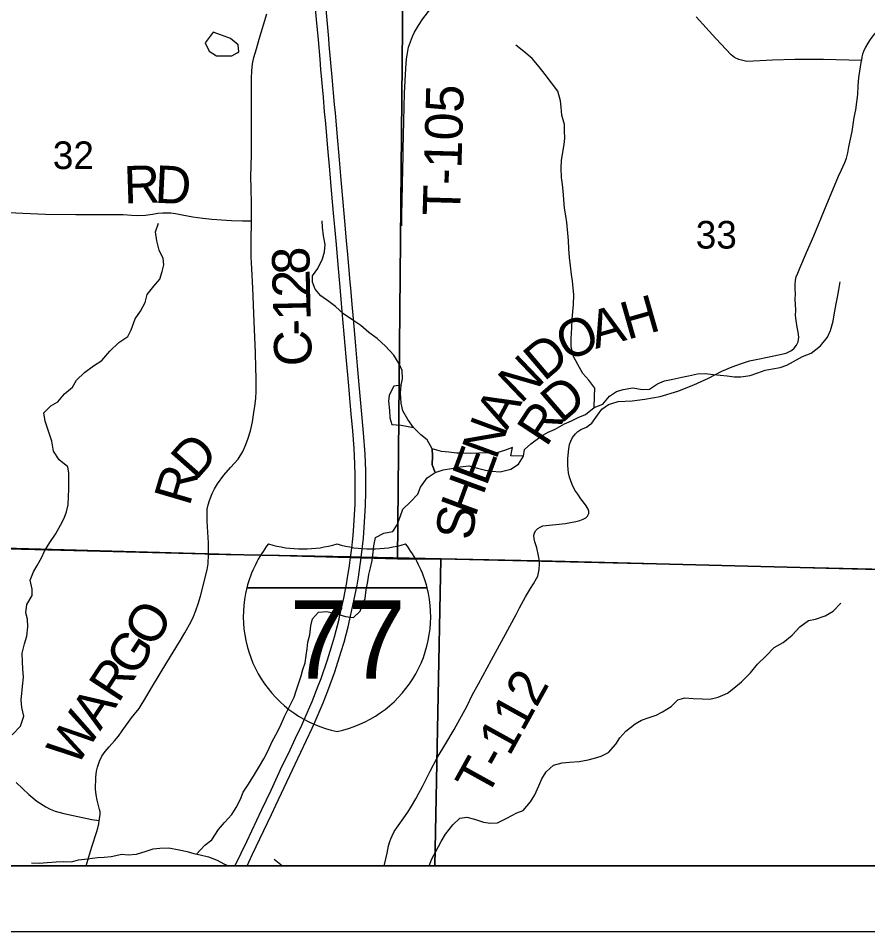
# Model space of a CAD drawing. Extents: x 0 to 34, y 0 to 22.
# Drawn here: x 28.471 to 29.759, y 14 to 15.384 of the extents above; entities that cross this region are included whole.
import ezdxf

# ---------------------------------------------------------------- set-up
doc = ezdxf.new("R2010")
doc.units = 0
for name, color, linetype in [('GM_X_Corporation', 7, 'Continuous'), ('GM_X_County_Road', 7, 'Continuous'), ('GM_X_County_Road_Text', 7, 'Continuous'), ('GM_X_Interstate_Location', 7, 'Continuous'), ('GM_X_Interstate_Route', 7, 'Continuous'), ('GM_X_Interstate_Shield', 7, 'Continuous'), ('GM_X_Minor_Lake', 7, 'Continuous'), ('GM_X_Minor_River', 7, 'Continuous'), ('GM_X_Section_Text', 7, 'Continuous'), ('GM_X_Township_Road', 7, 'Continuous'), ('GM_X_Township_Road_Text', 7, 'Continuous'), ('SH_Data', 7, 'Continuous')]:
    doc.layers.add(name, color=color, linetype=linetype)

msp = doc.modelspace()

# ---------------------------------------------------------------- linework, layer by layer
at = {"layer": 'GM_X_Corporation'}
for points in [[(23.5167, 14.1), (30.3167, 14.1), (30.3167, 18.565), (30.101, 18.5701), (29.6772, 18.5786), (29.6561, 18.5791), (29.0074, 18.5935), (28.7772, 18.6028), (28.3421, 18.6121), (27.3971, 18.6436), (27.1064, 18.6537), (27.1039, 18.5696), (27.0944, 18.0731), (27.0775, 16.888), (27.0694, 16.6556), (27.0676, 16.5549), (27.052, 15.403), (27.043, 14.755), (27.046, 14.6155), (27.01, 14.6164), (26.6535, 14.621)], [(27.0676, 16.5549), (27.052, 15.403), (27.043, 14.755), (27.046, 14.6155), (27.2076, 14.6118), (27.2151, 14.6117), (27.2601, 14.6106), (27.262, 14.6106), (27.3217, 14.6092), (27.3244, 14.6092), (28.7538, 14.5726), (28.7592, 14.5724), (28.9743, 14.568), (28.9779, 14.5679), (28.9904, 14.5676), (29.257, 14.5621), (29.2606, 14.562), (30.0913, 14.5411), (30.0947, 14.5411), (30.3167, 14.5373), (30.3167, 18.565)], [(26.0358, 14.1), (30.3167, 14.1), (30.3167, 14.5373), (30.0947, 14.5411), (30.0913, 14.5411), (29.2606, 14.562), (29.257, 14.5621), (28.9904, 14.5676), (28.9779, 14.5679), (28.9743, 14.568), (28.7592, 14.5724), (28.7538, 14.5726), (27.3244, 14.6092), (27.3217, 14.6092), (27.262, 14.6106), (27.2601, 14.6106), (27.2151, 14.6117), (27.2076, 14.6118), (27.046, 14.6155), (27.01, 14.6164), (26.6535, 14.621)]]:
    msp.add_lwpolyline(points, dxfattribs=at)
for points in [[(29.0554, 15.5858), (29.0455, 14.5648), (28.107, 14.591), (28.0653, 14.5914), (28.0603, 15.6194)], [(30.0852, 15.5935), (30.0916, 14.542), (29.1115, 14.5644), (29.0455, 14.5648), (29.0554, 15.5858)], [(28.0946, 14.1), (29.1022, 14.1), (29.1115, 14.5644), (29.0455, 14.5648), (28.107, 14.591)], [(29.1022, 14.1), (30.0878, 14.1), (30.0916, 14.542), (29.1115, 14.5644)]]:
    msp.add_lwpolyline(points, close=True, dxfattribs=at)
at = {"layer": 'GM_X_County_Road'}
for points in [[(29.8077, 15.4032), (29.7862, 15.3803), (29.7766, 15.3701), (29.7665, 15.3579), (29.7621, 15.3522), (29.7585, 15.3469), (29.755, 15.3404), (29.7523, 15.3341), (29.7506, 15.3298), (29.7497, 15.3262), (29.749, 15.3205), (29.6916, 15.322), (29.6482, 15.3218), (29.6144, 15.3211), (29.5752, 15.3187), (29.5633, 15.3221), (29.5567, 15.3252), (29.5516, 15.3291), (29.5282, 15.3538), (29.4987, 15.3865)], [(28.7593, 14.5748), (28.7593, 14.5894), (28.7579, 14.6137), (28.7574, 14.6225), (28.757, 14.6317), (28.7574, 14.6404), (28.7586, 14.6468), (28.7607, 14.6535), (28.7648, 14.6643), (28.7683, 14.6714), (28.773, 14.679), (28.7824, 14.6921), (28.7926, 14.7036), (28.8039, 14.716), (28.8114, 14.7277), (28.8149, 14.7361), (28.819, 14.7465), (28.8229, 14.7589), (28.8258, 14.7726), (28.8277, 14.7871), (28.8296, 14.7966), (28.831, 14.808), (28.8313, 14.8195), (28.8314, 14.8277), (28.8312, 14.8392), (28.831, 14.8544), (28.8306, 14.8778), (28.8283, 14.9244), (28.8265, 14.9756), (28.8247, 15.0047), (28.8239, 15.023), (28.8238, 15.0466), (28.8245, 15.0776), (28.8246, 15.1051), (28.8236, 15.1457), (28.8238, 15.1594), (28.8243, 15.1792), (28.8244, 15.2105), (28.8246, 15.2388), (28.8244, 15.2713), (28.8244, 15.2857), (28.8245, 15.2937), (28.8247, 15.3047), (28.8261, 15.3155), (28.828, 15.3249), (28.8318, 15.338), (28.8362, 15.3529), (28.8476, 15.3911)], [(28.583, 14.1304), (28.5892, 14.1502), (28.5913, 14.1571), (28.5928, 14.1633), (28.5934, 14.1686), (28.595, 14.1772), (28.5947, 14.1818), (28.5941, 14.1854), (28.5902, 14.1994), (28.5889, 14.2077), (28.5877, 14.216), (28.5886, 14.2341), (28.5896, 14.2434), (28.5911, 14.2494), (28.594, 14.2583), (28.5973, 14.266), (28.6024, 14.2731), (28.6084, 14.2801), (28.6168, 14.2892), (28.6228, 14.2963), (28.6284, 14.3043), (28.6425, 14.324), (28.6539, 14.3385), (28.664, 14.3548), (28.6742, 14.372), (28.6961, 14.4082), (28.7154, 14.4393), (28.7235, 14.4528), (28.7327, 14.47), (28.7362, 14.4777), (28.7401, 14.4871), (28.7435, 14.4969), (28.7469, 14.5087), (28.757, 14.5483), (28.7585, 14.5574), (28.7594, 14.5719), (28.7593, 14.5748)], [(28.4674, 14.2264), (28.4869, 14.2081), (28.499, 14.1981), (28.5126, 14.1894), (28.5191, 14.1858), (28.5265, 14.1826), (28.5397, 14.1793), (28.5821, 14.1703), (28.5934, 14.1686)], [(28.5739, 14.1), (28.5768, 14.11), (28.5803, 14.122), (28.583, 14.1304)]]:
    msp.add_lwpolyline(points, dxfattribs=at)
at = {"layer": 'GM_X_Interstate_Route'}
for points in [[(28.7997, 14.1), (28.8003, 14.1012), (28.8173, 14.137), (28.8399, 14.1852), (28.854, 14.2148), (28.8711, 14.2514), (28.8804, 14.2701), (28.8913, 14.2936), (28.9005, 14.3133), (28.9035, 14.3199), (28.9161, 14.3491), (28.9254, 14.3725), (28.9299, 14.384), (28.9395, 14.412), (28.9458, 14.4316), (28.9502, 14.4467), (28.9571, 14.4739), (28.9579, 14.4775), (28.9642, 14.5053), (28.9688, 14.5295), (28.9694, 14.5332), (28.9729, 14.5549), (28.9745, 14.5674), (28.9763, 14.5811), (28.9778, 14.5954), (28.9789, 14.6073), (28.9814, 14.6481), (28.9817, 14.6738), (28.9815, 14.6917), (28.9811, 14.7092), (28.9798, 14.7326), (28.9779, 14.7589), (28.9755, 14.7848), (28.9736, 14.8079), (28.9725, 14.8211), (28.9719, 14.8272), (28.968, 14.8714), (28.9666, 14.8885), (28.965, 14.9055), (28.9619, 14.9402), (28.9593, 14.971), (28.9552, 15.0167), (28.9532, 15.0414), (28.9507, 15.0685), (28.9493, 15.0836), (28.9458, 15.1234), (28.9431, 15.1548), (28.9403, 15.1874), (28.9368, 15.225), (28.9351, 15.2427), (28.9333, 15.2646), (28.9296, 15.307), (28.9284, 15.3225), (28.9257, 15.3515), (28.9229, 15.3828), (28.921, 15.4055)], [(28.8176, 14.1), (28.8255, 14.1167), (28.8546, 14.1778), (28.8611, 14.192), (28.8866, 14.2455), (28.8905, 14.2539), (28.9164, 14.3087), (28.921, 14.3188), (28.9328, 14.3469), (28.9401, 14.3651), (28.9507, 14.3937), (28.9605, 14.4246), (28.9646, 14.4391), (28.9708, 14.462), (28.9736, 14.4735), (28.9772, 14.4899), (28.9812, 14.5088), (28.9843, 14.525), (28.9864, 14.5375), (28.9906, 14.5671), (28.9942, 14.5967), (28.9964, 14.6294), (28.997, 14.6462), (28.9977, 14.6662), (28.9975, 14.6985), (28.9966, 14.7236), (28.9942, 14.756), (28.991, 14.7902), (28.9877, 14.8288), (28.9852, 14.8579), (28.9826, 14.8882), (28.9788, 14.9288), (28.977, 14.9505), (28.9748, 14.9752), (28.9739, 14.9845), (28.9703, 15.0262), (28.9684, 15.0469), (28.9661, 15.077), (28.9634, 15.1056), (28.9604, 15.1397), (28.9577, 15.1698), (28.9541, 15.2103), (28.9515, 15.2409), (28.9502, 15.2537), (28.9465, 15.2953), (28.9423, 15.3442), (28.9414, 15.3536), (28.9371, 15.4037)]]:
    msp.add_lwpolyline(points, dxfattribs=at)
at = {"layer": 'GM_X_Interstate_Shield'}
for p, q in [((28.8174, 14.5213), (29.0906, 14.5213)), ((29.0906, 14.5213), (28.8174, 14.5213)), ((29.0906, 14.5213), (28.8174, 14.5213))]:
    msp.add_line(p, q, dxfattribs=at)
for centre, start, end in [((28.9895, 14.4777), 141.669, 165.8066), ((28.9021, 14.7577), 253.0091, 286.9909), ((29.0059, 14.7577), 253.0091, 286.9909), ((28.9185, 14.4777), 14.1934, 38.331), ((28.9895, 14.4777), 165.8066, 258.463), ((28.9185, 14.4777), 281.537, 14.1934)]:
    msp.add_arc(centre, 0.1776, start, end, dxfattribs=at)
at = {"layer": 'GM_X_Minor_Lake'}
for points in [[(28.7663, 15.3632), (28.7543, 15.3473), (28.7604, 15.3348), (28.7714, 15.3276), (28.7945, 15.3277), (28.8027, 15.332)], [(28.8027, 15.332), (28.8054, 15.3334), (28.8043, 15.344), (28.7925, 15.3539), (28.7789, 15.3587), (28.7663, 15.3632)], [(29.0515, 14.8282), (29.0402, 14.827), (29.033, 14.8134), (29.0319, 14.8039), (29.0335, 14.7899), (29.0343, 14.7789), (29.0369, 14.7686), (29.051, 14.7679), (29.0699, 14.7642)], [(29.0699, 14.7642), (29.0615, 14.7763), (29.0539, 14.7896), (29.0512, 14.8009), (29.0504, 14.8161), (29.0515, 14.8282)], [(29.0984, 14.7321), (29.0988, 14.7211), (29.0981, 14.7074), (29.103, 14.6961), (29.1148, 14.6999), (29.1276, 14.7022), (29.1409, 14.7046), (29.1537, 14.7061), (29.167, 14.7028), (29.1791, 14.6994), (29.1886, 14.6979), (29.2011, 14.6972), (29.2177, 14.701), (29.2291, 14.7087), (29.2366, 14.7208)], [(29.2366, 14.7208), (29.2177, 14.7215), (29.2199, 14.7337), (29.2078, 14.7291), (29.1961, 14.726), (29.1828, 14.7256), (29.1692, 14.7255), (29.1567, 14.7247), (29.1465, 14.7254), (29.1355, 14.7254), (29.1234, 14.7269), (29.1124, 14.7276), (29.0984, 14.7321)]]:
    msp.add_lwpolyline(points, dxfattribs=at)
at = {"layer": 'GM_X_Minor_River'}
for points in [[(29.3436, 14.7944), (29.3443, 14.8114), (29.345, 14.8236), (29.3355, 14.8357), (29.3267, 14.8462), (29.3191, 14.8595), (29.3127, 14.8716), (29.3092, 14.8871), (29.3092, 14.8989), (29.3099, 14.9152), (29.3106, 14.9284), (29.3117, 14.9394), (29.3124, 14.9501), (29.3128, 14.9656), (29.312, 14.9755), (29.3108, 14.9864), (29.3096, 14.9959), (29.3081, 15.0092), (29.3065, 15.0217), (29.3054, 15.0349), (29.3049, 15.0478), (29.3038, 15.0588), (29.3026, 15.0751), (29.301, 15.085), (29.2991, 15.0967), (29.2979, 15.1096), (29.2968, 15.1229), (29.2956, 15.1323), (29.2944, 15.1429), (29.2936, 15.157), (29.2944, 15.1691), (29.2962, 15.1816), (29.2984, 15.193), (29.2996, 15.2029), (29.2991, 15.2139), (29.2987, 15.2233), (29.2949, 15.2377), (29.2937, 15.2498), (29.2929, 15.2593), (29.2887, 15.2741), (29.2789, 15.2866), (29.2697, 15.2994), (29.2606, 15.3108), (29.25, 15.3236), (29.2371, 15.3342), (29.2253, 15.3436)], [(29.103, 14.6961), (29.0981, 14.7074), (29.0988, 14.7211), (29.0984, 14.7321), (29.0908, 14.7457), (29.0813, 14.7529), (29.0699, 14.7642), (29.0615, 14.7763), (29.0539, 14.7896), (29.0512, 14.8009), (29.0504, 14.8161), (29.0515, 14.8282), (29.0534, 14.8381), (29.053, 14.8506), (29.048, 14.8608), (29.04, 14.8737), (29.0275, 14.8876), (29.015, 14.899), (29.0021, 14.9084), (28.9899, 14.919), (28.9763, 14.9277), (28.9637, 14.9363), (28.9516, 14.9477), (28.9417, 14.9552), (28.9296, 14.9635), (28.9208, 14.9741), (28.9166, 14.9843), (28.917, 14.9942), (28.9249, 15.0052), (28.9321, 15.0196), (28.9351, 15.0302), (28.9362, 15.0416), (28.9335, 15.0549), (28.9319, 15.0678), (28.9315, 15.0776)], [(28.4617, 14.2984), (28.4742, 14.3117), (28.479, 14.3265), (28.476, 14.3398), (28.4752, 14.3511), (28.4774, 14.3716), (28.4789, 14.3857), (28.4777, 14.3985), (28.4773, 14.4088), (28.4769, 14.422), (28.4802, 14.4361), (28.4836, 14.4479), (28.4851, 14.4619), (28.4846, 14.4736), (28.4823, 14.4831), (28.4838, 14.496), (28.4921, 14.5097), (28.4921, 14.5192), (28.489, 14.5328), (28.4939, 14.5453), (28.4995, 14.5552), (28.506, 14.5666), (28.5105, 14.5768), (28.5188, 14.5901), (28.527, 14.6027), (28.535, 14.616), (28.5402, 14.627), (28.544, 14.6365), (28.5462, 14.6471), (28.5469, 14.66), (28.5473, 14.6702), (28.5476, 14.682), (28.5476, 14.6949), (28.5461, 14.7047), (28.5328, 14.7153), (28.5244, 14.7282), (28.5217, 14.7433), (28.5167, 14.7588), (28.5118, 14.7736), (28.5095, 14.7865), (28.5204, 14.7971), (28.531, 14.8032), (28.5408, 14.8154), (28.5529, 14.8253), (28.5593, 14.836), (28.5714, 14.8477), (28.5846, 14.8577), (28.5974, 14.8657), (28.6095, 14.8797), (28.6235, 14.893), (28.6367, 14.9022), (28.642, 14.9124), (28.648, 14.9291), (28.6559, 14.9405), (28.6634, 14.9535), (28.6661, 14.966), (28.6762, 14.9785), (28.6853, 14.9892), (28.689, 15.0006), (28.6913, 15.0108), (28.6905, 15.0203), (28.6844, 15.0328), (28.681, 15.0472), (28.6786, 15.0608), (28.6835, 15.0737)], [(29.6141, 14.8529), (29.6258, 14.8552), (29.636, 14.8587), (29.6459, 14.864), (29.6599, 14.8717), (29.6727, 14.877), (29.6867, 14.8881), (29.6973, 14.901), (29.7021, 14.9112), (29.7063, 14.9256), (29.7081, 14.9382), (29.7107, 14.9514), (29.7126, 14.9617), (29.7145, 14.9727), (29.7167, 14.9852)], [(28.7408, 14.1178), (28.7534, 14.1311), (28.7643, 14.1395), (28.7741, 14.1547), (28.7836, 14.1657), (28.7945, 14.1775), (28.8009, 14.1885), (28.8077, 14.201), (28.8118, 14.2117), (28.8186, 14.2223), (28.8273, 14.2356), (28.8367, 14.2508), (28.8431, 14.2622), (28.8491, 14.2736), (28.8559, 14.2884), (28.8638, 14.3029), (28.8691, 14.3146), (28.8743, 14.326), (28.8792, 14.3363), (28.889, 14.3553), (28.892, 14.3651), (28.8961, 14.3773), (28.8995, 14.3879), (28.9021, 14.3974), (28.9059, 14.4073), (28.9074, 14.4186), (28.9088, 14.4289), (28.9099, 14.4387), (28.9126, 14.4501), (28.9144, 14.4638), (28.917, 14.474), (28.9257, 14.4843), (28.9386, 14.4851), (28.9518, 14.4821), (28.967, 14.478), (28.9791, 14.4761), (28.9893, 14.4857), (28.9927, 14.4952), (28.9965, 14.505), (28.9983, 14.5183), (29.0005, 14.5308), (29.0024, 14.5414), (29.005, 14.5513), (29.0073, 14.5627), (29.0087, 14.5752), (29.0098, 14.5851), (29.0125, 14.5976), (29.0249, 14.6041), (29.0386, 14.6068), (29.045, 14.6167), (29.0495, 14.6288), (29.0536, 14.6406), (29.0649, 14.6508), (29.0766, 14.6634), (29.0804, 14.674), (29.0906, 14.6877), (29.103, 14.6961), (29.1148, 14.6999), (29.1276, 14.7022), (29.1409, 14.7046), (29.1537, 14.7061), (29.167, 14.7028), (29.1791, 14.6994), (29.1886, 14.6979), (29.2011, 14.6972), (29.2177, 14.701), (29.2291, 14.7087), (29.2366, 14.7208), (29.2381, 14.7311), (29.2479, 14.7394), (29.2634, 14.7512), (29.274, 14.757), (29.2846, 14.7619), (29.2989, 14.7696), (29.3095, 14.7741), (29.3194, 14.7795), (29.3307, 14.7841), (29.3436, 14.7944), (29.3572, 14.7997), (29.367, 14.8119), (29.3779, 14.8187), (29.3878, 14.8218), (29.4025, 14.8241), (29.4169, 14.8219), (29.4279, 14.8223), (29.44, 14.8303), (29.4502, 14.8349), (29.4631, 14.8372), (29.4767, 14.8403), (29.4869, 14.8426), (29.5005, 14.8457), (29.5119, 14.8461), (29.5248, 14.8447), (29.5346, 14.8435), (29.5452, 14.8424), (29.5562, 14.841), (29.5664, 14.841), (29.5801, 14.8429), (29.5918, 14.8472), (29.6031, 14.851), (29.6141, 14.8529)], [(29.0937, 14.1), (29.0976, 14.1103), (29.104, 14.1217), (29.1119, 14.1369), (29.1183, 14.1479), (29.1296, 14.162), (29.1402, 14.1723), (29.1508, 14.1734), (29.1625, 14.1705), (29.1762, 14.1663), (29.1868, 14.1645), (29.1974, 14.1649), (29.2114, 14.1721), (29.2265, 14.1802), (29.2363, 14.1836), (29.2473, 14.1969), (29.2537, 14.2076), (29.2601, 14.2212), (29.2646, 14.2315), (29.271, 14.2425), (29.2823, 14.2524), (29.2952, 14.2559), (29.3065, 14.257), (29.3209, 14.2578), (29.3345, 14.2605), (29.3444, 14.2629), (29.3546, 14.2659), (29.3656, 14.2716), (29.3769, 14.2842), (29.3829, 14.2941), (29.3916, 14.304), (29.4059, 14.315), (29.4158, 14.3204), (29.4271, 14.3249), (29.4377, 14.3284), (29.4475, 14.3334), (29.4604, 14.3414), (29.4706, 14.3513), (29.4812, 14.3547), (29.4937, 14.3536), (29.5077, 14.3529), (29.5194, 14.3526), (29.5319, 14.3553), (29.5459, 14.3617), (29.5557, 14.369), (29.567, 14.3789), (29.5806, 14.3926), (29.5912, 14.4055), (29.6044, 14.4181), (29.6169, 14.431), (29.6301, 14.4382), (29.6441, 14.4497), (29.6554, 14.4622), (29.6686, 14.4717), (29.6792, 14.4737), (29.694, 14.479), (29.7061, 14.4859), (29.7178, 14.4981)], [(28.4907, 14.1044), (28.5024, 14.104), (28.5145, 14.1048), (28.5282, 14.106), (28.5399, 14.1064), (28.5516, 14.1057), (28.5622, 14.1088), (28.5755, 14.1107), (28.591, 14.1127), (28.6008, 14.1131), (28.6118, 14.1139), (28.6277, 14.1174), (28.6375, 14.1166), (28.65, 14.1178), (28.6648, 14.1221), (28.6754, 14.1255), (28.6856, 14.1267), (28.6989, 14.1271), (28.7148, 14.1241), (28.7269, 14.1215), (28.7371, 14.1185), (28.7466, 14.1167), (28.7591, 14.1137), (28.7724, 14.1084), (28.7822, 14.1031), (28.7894, 14.1)]]:
    msp.add_lwpolyline(points, dxfattribs=at)
at = {"layer": 'GM_X_Township_Road'}
for points in [[(29.0544, 15.1854), (29.0553, 15.2283), (29.0562, 15.2707), (29.0582, 15.3082), (29.0595, 15.3227), (29.0608, 15.3314), (29.0626, 15.3404), (29.0682, 15.3566), (29.0717, 15.3633), (29.0775, 15.3733), (29.0839, 15.3838), (29.0962, 15.3993), (29.1109, 15.4152), (29.1195, 15.425)], [(29.2607, 14.5517), (29.261, 14.5547), (29.2608, 14.5614), (29.2594, 14.5698), (29.2568, 14.5816), (29.2539, 14.591), (29.2528, 14.5956), (29.2526, 14.6011), (29.2532, 14.604), (29.2549, 14.6074), (29.2585, 14.6113), (29.2619, 14.6132), (29.2659, 14.615), (29.3002, 14.6188), (29.3079, 14.62), (29.316, 14.6217), (29.3222, 14.6234), (29.3269, 14.6251), (29.3311, 14.6272), (29.3335, 14.63), (29.3357, 14.6339), (29.3357, 14.6372), (29.3349, 14.6406), (29.3318, 14.6456), (29.3276, 14.6512), (29.3234, 14.6559), (29.3191, 14.6632), (29.3147, 14.6691), (29.3103, 14.6778), (29.3064, 14.6887), (29.305, 14.6954), (29.3045, 14.7004), (29.3039, 14.707), (29.3038, 14.7119), (29.3037, 14.7174), (29.3053, 14.7317), (29.3063, 14.7384), (29.3083, 14.7435), (29.3109, 14.7488), (29.3154, 14.7547), (29.3191, 14.7583), (29.3234, 14.761), (29.3322, 14.7649), (29.3366, 14.7681), (29.3403, 14.7709), (29.349, 14.7829), (29.3553, 14.7918), (29.3657, 14.799), (29.38, 14.8036), (29.4012, 14.8045), (29.4205, 14.8069), (29.4441, 14.8112), (29.4706, 14.8191), (29.4951, 14.829), (29.5173, 14.8391), (29.5375, 14.8494), (29.5529, 14.8562), (29.5673, 14.8613), (29.5795, 14.8652), (29.5917, 14.8679), (29.6068, 14.8707), (29.6234, 14.8742), (29.6348, 14.8771), (29.6429, 14.8811), (29.6472, 14.8845), (29.6508, 14.889), (29.6531, 14.8939), (29.6539, 14.9011), (29.6529, 14.9088), (29.6517, 14.9164), (29.6498, 14.9263), (29.6492, 14.934), (29.6494, 14.9419), (29.6487, 14.9589), (29.6492, 14.967), (29.6484, 14.9744), (29.6484, 14.9804), (29.6492, 14.9874), (29.6503, 14.9924), (29.6525, 14.9983), (29.6556, 15.0055), (29.6655, 15.0296), (29.6767, 15.0547), (29.6956, 15.1001), (29.7143, 15.1451), (29.7188, 15.1547), (29.7238, 15.1657), (29.7263, 15.1722), (29.7286, 15.1807), (29.7298, 15.1895), (29.7347, 15.2129), (29.738, 15.2338), (29.7406, 15.2456), (29.7434, 15.2687), (29.744, 15.2818), (29.7452, 15.2949), (29.749, 15.3205)], [(29.0523, 15.0697), (29.0522, 15.0791), (29.0523, 15.0882), (29.0526, 15.1064), (29.0534, 15.1336), (29.0542, 15.1766), (29.0544, 15.1854)], [(28.4566, 15.09), (28.4779, 15.0892), (28.5119, 15.0876), (28.558, 15.0868), (28.5881, 15.0871), (28.6065, 15.0869), (28.6298, 15.087), (28.6426, 15.086), (28.6514, 15.0855), (28.6638, 15.086), (28.6744, 15.0875), (28.6822, 15.0888), (28.6901, 15.0893), (28.696, 15.0895), (28.7019, 15.0893), (28.7093, 15.0884), (28.7193, 15.0867), (28.7352, 15.0834), (28.7507, 15.0813), (28.764, 15.0801), (28.7787, 15.0788), (28.7939, 15.0779), (28.8107, 15.0775), (28.8245, 15.0776)], [(29.0254, 14.1), (29.0259, 14.102), (29.028, 14.1103), (29.03, 14.1192), (29.0322, 14.1301), (29.034, 14.1368), (29.0354, 14.141), (29.0375, 14.1455), (29.0404, 14.1518), (29.0615, 14.1813), (29.0671, 14.1901), (29.0736, 14.2015), (29.0782, 14.2099), (29.0836, 14.2203), (29.095, 14.2434), (29.1058, 14.2638), (29.1189, 14.2855), (29.1316, 14.3063), (29.1511, 14.3423), (29.1591, 14.3586), (29.1683, 14.3758), (29.188, 14.4119), (29.2065, 14.4456), (29.2254, 14.4809), (29.2308, 14.491), (29.2397, 14.5076), (29.2472, 14.52), (29.2517, 14.5271), (29.2565, 14.5351), (29.2583, 14.5389), (29.2596, 14.5437), (29.2605, 14.5488), (29.2607, 14.5517)], [(28.8589, 14.1102), (28.8664, 14.1038), (28.8715, 14.1)]]:
    msp.add_lwpolyline(points, dxfattribs=at)
at = {"layer": 'SH_Data'}
for points in [[(23.4167, 21), (30.4167, 21), (30.4167, 14), (23.4167, 14)], [(23.5167, 20.9), (30.3167, 20.9), (30.3167, 14.1), (23.5167, 14.1)]]:
    msp.add_lwpolyline(points, close=True, dxfattribs=at)

# ---------------------------------------------------------------- texts
at = {"layer": 'GM_X_County_Road_Text'}
for s, rotation, p in [('8', 90.9866, (28.9127, 14.9964)), ('2', 91.2111, (28.9134, 14.9618)), ('1', 91.3298, (28.9142, 14.9271)), ('-', 91.4141, (28.9148, 14.904)), ('C', 91.4422, (28.916, 14.8577)), ('D', 48.5156, (28.7403, 14.6828)), ('R', 73.5748, (28.7303, 14.6437)), ('O', 59.3741, (28.6766, 14.4285)), ('G', 56.9469, (28.6479, 14.3844)), ('R', 56.8652, (28.6224, 14.3452)), ('A', 56.7204, (28.5949, 14.3033)), ('W', 56.5977, (28.5585, 14.2482))]:
    msp.add_text(s, height=0.0568, rotation=rotation, dxfattribs=at).set_placement(p)
at = {"layer": 'GM_X_Interstate_Location'}
for s in ['-', '.', ',']:
    msp.add_text(s, height=0.000189, dxfattribs=at).set_placement((28.954, 14.4457))
msp.add_text('77', height=0.000189, rotation=0, dxfattribs=at).set_placement((28.9153, 14.4065))
at = {"layer": 'GM_X_Interstate_Shield'}
msp.add_text('77', height=0.11837, dxfattribs=at).set_placement((28.8821, 14.3837))
at = {"layer": 'GM_X_Section_Text'}
for s, p in [('32', (28.5232, 15.1559)), ('33', (29.4978, 15.0354))]:
    msp.add_text(s, height=0.04186, rotation=0, dxfattribs=at).set_placement(p)
at = {"layer": 'GM_X_Township_Road_Text'}
for s, height, rotation, p in [('T-105', 0.05682, 88.3577, (29.1405, 15.0847)), ('R', 0.0568, 1.8465, (28.6316, 15.1035)), ('D', 0.0568, 357.256, (28.677, 15.105)), ('H', 0.0568, 15.9459, (29.394, 14.8969)), ('A', 0.0568, 16.0209, (29.346, 14.8831)), ('O', 0.0568, 24.5217, (29.3026, 14.8632)), ('D', 0.0568, 40.3508, (29.268, 14.833)), ('N', 0.0568, 43.7558, (29.2325, 14.799)), ('D', 0.0568, 40.87, (29.2942, 14.7692)), ('A', 0.0568, 61.6704, (29.2116, 14.7587)), ('R', 0.0568, 56.7819, (29.2713, 14.7333)), ('N', 0.0568, 69.762, (29.1952, 14.7138)), ('E', 0.0568, 69.7745, (29.1805, 14.6739)), ('H', 0.0568, 69.8933, (29.1633, 14.627)), ('S', 0.0568, 83.017, (29.1595, 14.5922)), ('T-112', 0.05682, 61.0546, (29.1807, 14.2018))]:
    msp.add_text(s, height=height, rotation=rotation, dxfattribs=at).set_placement(p)

doc.saveas('drawing.dxf')
